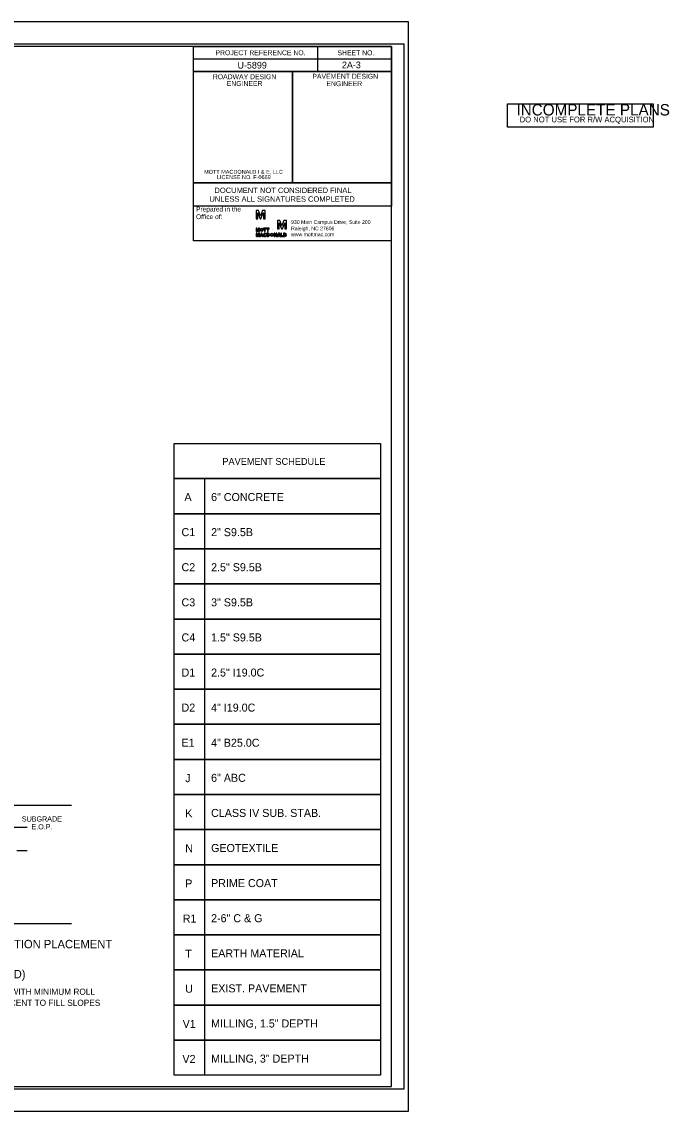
# Model space of a CAD drawing. Extents: x 1904401 to 1905163, y 193929 to 194736.
# Drawn here: x 1904969.4 to 1905100.1, y 194023.4 to 194243.4 of the extents above; entities that cross this region are included whole.
import ezdxf

# ---------------------------------------------------------------- set-up
doc = ezdxf.new("R2010")
doc.units = 0
for name, color, linetype in [('Old_Level_2', 7, 'Continuous'), ('Old_Level_42', 7, 'Continuous'), ('Old_Level_45', 7, 'Continuous'), ('Prop Dimension Text', 7, 'Continuous'), ('Prop Pavement Schedule Description CELL', 7, 'Continuous'), ('Sheet Cutting Line CELL', 7, 'Continuous'), ('Sheet Data Field CELL', 7, 'Continuous'), ('Sheet Plot Border Inside CELL', 7, 'Continuous'), ('Sheet Plot Border Outside CELL', 7, 'Continuous'), ('Sheet Sticker Exception Certification CELL', 7, 'Continuous'), ('Sheet Sticker Incomplete CELL', 7, 'Continuous'), ('Sheet Typical CELL', 7, 'Continuous')]:
    doc.layers.add(name, color=color, linetype=linetype)

msp = doc.modelspace()

# ---------------------------------------------------------------- linework, layer by layer
at = {"layer": 'Old_Level_2'}
for p, q in [((1905017.2, 194205.31), (1905016.7, 194205.31)), ((1905016.7, 194205.31), (1905016.7, 194203.62)), ((1905017.61, 194204.26), (1905017.2, 194205.31)), ((1905018.03, 194205.31), (1905017.62, 194204.26)), ((1905018.54, 194205.31), (1905018.03, 194205.31)), ((1905018.54, 194203.62), (1905018.54, 194205.31)), ((1905016.7, 194203.62), (1905017.06, 194203.62)), ((1905017.06, 194203.62), (1905017.06, 194204.84)), ((1905017.06, 194204.84), (1905017.06, 194204.84)), ((1905017.06, 194204.84), (1905017.54, 194203.62)), ((1905017.54, 194203.62), (1905017.7, 194203.62)), ((1905017.61, 194204.25), (1905017.61, 194204.26)), ((1905017.62, 194204.25), (1905017.61, 194204.25)), ((1905017.62, 194204.26), (1905017.62, 194204.25)), ((1905017.7, 194203.62), (1905018.17, 194204.84)), ((1905018.17, 194204.84), (1905018.18, 194204.84)), ((1905018.18, 194204.84), (1905018.18, 194203.62)), ((1905018.18, 194203.62), (1905018.54, 194203.62)), ((1905021.52, 194203.34), (1905021.02, 194203.34)), ((1905021.02, 194203.34), (1905021.02, 194201.64)), ((1905021.38, 194201.64), (1905021.38, 194202.86)), ((1905021.38, 194202.86), (1905021.38, 194202.86)), ((1905021.38, 194202.86), (1905021.86, 194201.64)), ((1905021.93, 194202.29), (1905021.52, 194203.34)), ((1905022.35, 194203.34), (1905021.94, 194202.29)), ((1905022.02, 194201.64), (1905022.49, 194202.86)), ((1905022.86, 194203.34), (1905022.35, 194203.34)), ((1905022.49, 194202.86), (1905022.5, 194202.86)), ((1905022.5, 194202.86), (1905022.5, 194201.64)), ((1905022.86, 194201.64), (1905022.86, 194203.34)), ((1905016.89, 194201.76), (1905016.7, 194201.76)), ((1905016.7, 194201.76), (1905016.7, 194201.11)), ((1905016.7, 194201.11), (1905016.83, 194201.11)), ((1905016.89, 194200.75), (1905016.7, 194200.75)), ((1905016.7, 194200.75), (1905016.7, 194200.1)), ((1905016.83, 194201.11), (1905016.83, 194201.57)), ((1905016.83, 194201.57), (1905016.84, 194201.57)), ((1905016.84, 194201.57), (1905017.02, 194201.11)), ((1905017.05, 194201.35), (1905016.89, 194201.76)), ((1905017.05, 194200.34), (1905016.89, 194200.75)), ((1905017.02, 194201.11), (1905017.08, 194201.11)), ((1905017.21, 194201.76), (1905017.05, 194201.35)), ((1905017.21, 194200.75), (1905017.05, 194200.34)), ((1905017.08, 194201.11), (1905017.27, 194201.57)), ((1905017.41, 194201.76), (1905017.21, 194201.76)), ((1905017.41, 194200.75), (1905017.21, 194200.75)), ((1905017.27, 194201.57), (1905017.27, 194201.57)), ((1905017.27, 194201.57), (1905017.27, 194201.11)), ((1905017.27, 194201.11), (1905017.41, 194201.11)), ((1905017.41, 194201.11), (1905017.41, 194201.76)), ((1905017.41, 194200.1), (1905017.41, 194200.75)), ((1905019.17, 194200.75), (1905018.88, 194200.75)), ((1905018.88, 194200.75), (1905018.88, 194200.41)), ((1905019.01, 194200.22), (1905019.01, 194200.63)), ((1905019.01, 194200.63), (1905019.17, 194200.63)), ((1905019.49, 194201.57), (1905019.5, 194201.57)), ((1905019.93, 194201.57), (1905019.93, 194201.57)), ((1905021.02, 194201.64), (1905021.38, 194201.64)), ((1905021.86, 194201.64), (1905022.02, 194201.64)), ((1905021.93, 194202.27), (1905021.93, 194202.29)), ((1905021.94, 194202.27), (1905021.93, 194202.27)), ((1905021.94, 194202.29), (1905021.94, 194202.27)), ((1905022.24, 194200.75), (1905022.24, 194200.75)), ((1905022.53, 194200.75), (1905022.24, 194200.75)), ((1905022.24, 194200.75), (1905022.24, 194200.41)), ((1905022.37, 194200.22), (1905022.37, 194200.63)), ((1905022.37, 194200.63), (1905022.53, 194200.63)), ((1905022.5, 194201.64), (1905022.86, 194201.64)), ((1905022.53, 194200.62), (1905022.53, 194200.62)), ((1905016.7, 194200.1), (1905016.83, 194200.1)), ((1905016.83, 194200.1), (1905016.83, 194200.57)), ((1905016.83, 194200.57), (1905016.84, 194200.57)), ((1905016.84, 194200.57), (1905017.02, 194200.1)), ((1905017.02, 194200.1), (1905017.08, 194200.1)), ((1905017.08, 194200.1), (1905017.27, 194200.57)), ((1905017.27, 194200.57), (1905017.27, 194200.57)), ((1905017.27, 194200.57), (1905017.27, 194200.1)), ((1905017.27, 194200.1), (1905017.41, 194200.1)), ((1905018.77, 194200.23), (1905018.66, 194200.29)), ((1905018.67, 194200.54), (1905018.79, 194200.59)), ((1905018.67, 194200.54), (1905018.79, 194200.59)), ((1905018.88, 194200.41), (1905018.88, 194200.1)), ((1905018.88, 194200.1), (1905019.17, 194200.1)), ((1905019.17, 194200.22), (1905019.01, 194200.22)), ((1905021.43, 194200.23), (1905021.32, 194200.29)), ((1905022.24, 194200.41), (1905022.24, 194200.1)), ((1905022.24, 194200.1), (1905022.53, 194200.1)), ((1905022.53, 194200.22), (1905022.37, 194200.22))]:
    msp.add_line(p, q, dxfattribs=at)
for points in [[(1905017.48, 194200.1), (1905017.64, 194200.1), (1905017.68, 194200.21), (1905017.96, 194200.21), (1905018, 194200.1), (1905018.15, 194200.1), (1905017.9, 194200.75), (1905017.73, 194200.75), (1905017.48, 194200.1)], [(1905017.72, 194200.33), (1905017.82, 194200.61), (1905017.93, 194200.33), (1905017.72, 194200.33)], [(1905018.22, 194201.64), (1905018.41, 194201.64), (1905018.41, 194201.11), (1905018.55, 194201.11), (1905018.55, 194201.64), (1905018.74, 194201.64), (1905018.74, 194201.76), (1905018.22, 194201.76), (1905018.22, 194201.64)], [(1905018.82, 194201.64), (1905019.01, 194201.64), (1905019.01, 194201.11), (1905019.15, 194201.11), (1905019.15, 194201.64), (1905019.33, 194201.64), (1905019.33, 194201.76), (1905018.82, 194201.76), (1905018.82, 194201.64)], [(1905020.47, 194200.52), (1905020.47, 194200.52), (1905020.78, 194200.1), (1905020.91, 194200.1), (1905020.91, 194200.75), (1905020.78, 194200.75), (1905020.78, 194200.34), (1905020.47, 194200.75), (1905020.34, 194200.75), (1905020.34, 194200.1), (1905020.47, 194200.1), (1905020.47, 194200.52)], [(1905020.99, 194200.1), (1905021.15, 194200.1), (1905021.19, 194200.21), (1905021.47, 194200.21), (1905021.51, 194200.1), (1905021.66, 194200.1), (1905021.42, 194200.75), (1905021.24, 194200.75), (1905020.99, 194200.1)], [(1905021.23, 194200.33), (1905021.33, 194200.61), (1905021.44, 194200.33), (1905021.23, 194200.33)], [(1905022.16, 194200.1), (1905022.16, 194200.21), (1905021.88, 194200.21), (1905021.88, 194200.75), (1905021.74, 194200.75), (1905021.74, 194200.1), (1905022.16, 194200.1)]]:
    msp.add_lwpolyline(points, dxfattribs=at)
msp.add_arc((1905022.53, 194200.42), 0.325, 270, 90, dxfattribs=at)
for centre, major_axis, ratio in [((1905017.85, 194201.43), (0, 0.325), 0.993118), ((1905017.85, 194201.43), (0, 0.211), 0.916103), ((1905019.9, 194200.42), (0, 0.325), 0.993118), ((1905019.9, 194200.42), (0, 0.211), 0.916103)]:
    msp.add_ellipse(centre, major_axis=major_axis, ratio=ratio, dxfattribs=at)
for centre, major_axis, ratio, start_param, end_param in [((1905018.51, 194200.42), (0, 0.325), 0.993118, 5.246647, 10.366427), ((1905018.51, 194200.42), (0, 0.211), 0.916103, 5.276876, 10.296021), ((1905019.17, 194200.42), (0, -0.324), 0.930276, 0, 3.141593), ((1905019.17, 194200.43), (0, -0.203), 0.900832, 0, 3.141593), ((1905022.53, 194200.43), (0, -0.203), 0.900832, 0, 3.141593)]:
    msp.add_ellipse(centre, major_axis=major_axis, ratio=ratio, start_param=start_param, end_param=end_param, dxfattribs=at)
at = {"layer": 'Old_Level_42'}
msp.add_lwpolyline([(1905044.05, 194199.18), (1905004.08, 194199.18), (1905004.08, 194206.23)], dxfattribs=at)
at = {"layer": 'Prop Dimension Text'}
for p, q in [((1904970.47, 194080.72), (1904967.5, 194080.72)), ((1904970.47, 194076.02), (1904968.39, 194076.02))]:
    msp.add_line(p, q, dxfattribs=at)
for points in [[(1904979.44, 194085.19), (1904951.83, 194085.19), (1904951.21, 194086.17), (1904950.82, 194084.34), (1904950.18, 194085.19), (1904924.97, 194085.19)], [(1904979.44, 194061.29), (1904951.83, 194061.29), (1904951.21, 194062.26), (1904950.82, 194060.44), (1904950.18, 194061.28), (1904924.97, 194061.28)]]:
    msp.add_lwpolyline(points, dxfattribs=at)
at = {"layer": 'Prop Pavement Schedule Description CELL'}
msp.add_lwpolyline([(1905000.16, 194158.28), (1905041.87, 194158.28), (1905041.87, 194151.19), (1905000.16, 194151.19)], close=True, dxfattribs=at)
for points in [[(1905006.34, 194144.1), (1905000.16, 194144.1), (1905000.16, 194151.19), (1905041.87, 194151.19), (1905041.87, 194144.1), (1905006.34, 194144.1), (1905006.34, 194151.19)], [(1905006.34, 194137.02), (1905000.16, 194137.02), (1905000.16, 194144.1), (1905041.87, 194144.1), (1905041.87, 194137.02), (1905006.34, 194137.02), (1905006.34, 194144.1)], [(1905006.34, 194129.93), (1905000.16, 194129.93), (1905000.16, 194137.02), (1905041.87, 194137.02), (1905041.87, 194129.93), (1905006.34, 194129.93), (1905006.34, 194137.02)], [(1905006.34, 194122.84), (1905000.16, 194122.84), (1905000.16, 194129.93), (1905041.87, 194129.93), (1905041.87, 194122.84), (1905006.34, 194122.84), (1905006.34, 194129.93)], [(1905006.34, 194115.76), (1905000.16, 194115.76), (1905000.16, 194122.84), (1905041.87, 194122.84), (1905041.87, 194115.76), (1905006.34, 194115.76), (1905006.34, 194122.84)], [(1905006.34, 194108.67), (1905000.16, 194108.67), (1905000.16, 194115.76), (1905041.87, 194115.76), (1905041.87, 194108.67), (1905006.34, 194108.67), (1905006.34, 194115.76)], [(1905006.34, 194101.58), (1905000.16, 194101.58), (1905000.16, 194108.67), (1905041.87, 194108.67), (1905041.87, 194101.58), (1905006.34, 194101.58), (1905006.34, 194108.67)], [(1905006.34, 194094.49), (1905000.16, 194094.49), (1905000.16, 194101.58), (1905041.87, 194101.58), (1905041.87, 194094.49), (1905006.34, 194094.49), (1905006.34, 194101.58)], [(1905006.34, 194087.41), (1905000.16, 194087.41), (1905000.16, 194094.49), (1905041.87, 194094.49), (1905041.87, 194087.41), (1905006.34, 194087.41), (1905006.34, 194094.49)], [(1905006.34, 194080.32), (1905000.16, 194080.32), (1905000.16, 194087.41), (1905041.87, 194087.41), (1905041.87, 194080.32), (1905006.34, 194080.32), (1905006.34, 194087.41)], [(1905006.34, 194073.23), (1905000.16, 194073.23), (1905000.16, 194080.32), (1905041.87, 194080.32), (1905041.87, 194073.23), (1905006.34, 194073.23), (1905006.34, 194080.32)], [(1905006.34, 194066.14), (1905000.16, 194066.14), (1905000.16, 194073.23), (1905041.87, 194073.23), (1905041.87, 194066.14), (1905006.34, 194066.14), (1905006.34, 194073.23)], [(1905006.34, 194059.06), (1905000.16, 194059.06), (1905000.16, 194066.14), (1905041.87, 194066.14), (1905041.87, 194059.06), (1905006.34, 194059.06), (1905006.34, 194066.14)], [(1905006.34, 194051.97), (1905000.16, 194051.97), (1905000.16, 194059.06), (1905041.87, 194059.06), (1905041.87, 194051.97), (1905006.34, 194051.97), (1905006.34, 194059.06)], [(1905006.34, 194044.88), (1905000.16, 194044.88), (1905000.16, 194051.97), (1905041.87, 194051.97), (1905041.87, 194044.88), (1905006.34, 194044.88), (1905006.34, 194051.97)], [(1905006.34, 194037.79), (1905000.16, 194037.79), (1905000.16, 194044.88), (1905041.87, 194044.88), (1905041.87, 194037.79), (1905006.34, 194037.79), (1905006.34, 194044.88)], [(1905006.34, 194030.71), (1905000.16, 194030.71), (1905000.16, 194037.79), (1905041.87, 194037.79), (1905041.87, 194030.71), (1905006.34, 194030.71), (1905006.34, 194037.79)]]:
    msp.add_lwpolyline(points, dxfattribs=at)
at = {"layer": 'Sheet Cutting Line CELL'}
for p, q in [((1905047.49, 194243.44), (1904710.69, 194243.44)), ((1904710.69, 194023.44), (1905047.49, 194023.44))]:
    msp.add_line(p, q, dxfattribs=at)
at = {"layer": 'Sheet Plot Border Inside CELL'}
msp.add_lwpolyline([(1905046.59, 194238.95), (1904713.29, 194238.95), (1904713.29, 194027.93), (1905046.59, 194027.93)], close=True, dxfattribs=at)
at = {"layer": 'Sheet Plot Border Outside CELL'}
msp.add_lwpolyline([(1905047.49, 194243.44), (1904710.69, 194243.44), (1904710.69, 194023.44), (1905047.49, 194023.44)], close=True, dxfattribs=at)
at = {"layer": 'Sheet Sticker Exception Certification CELL'}
for p, q in [((1905004.08, 194206.23), (1905004.08, 194210.93)), ((1905004.08, 194210.93), (1905044.09, 194210.93)), ((1905044.09, 194210.93), (1905044.09, 194206.23)), ((1905044.09, 194206.23), (1905004.08, 194206.23))]:
    msp.add_line(p, q, dxfattribs=at)
at = {"layer": 'Sheet Sticker Incomplete CELL'}
msp.add_lwpolyline([(1905067.5, 194222.18), (1905067.5, 194226.88), (1905096.9, 194226.88), (1905096.9, 194222.18)], close=True, dxfattribs=at)
at = {"layer": 'Sheet Typical CELL'}
for p, q in [((1905029.09, 194238.43), (1905029.09, 194233.43)), ((1905004.08, 194235.93), (1905044.09, 194235.93)), ((1905024.09, 194233.43), (1905024.09, 194210.94))]:
    msp.add_line(p, q, dxfattribs=at)
for points in [[(1905044.09, 194238.44), (1904744.09, 194238.44), (1904744.09, 194028.44), (1905044.09, 194028.44)], [(1905004.08, 194238.44), (1905044.09, 194238.44), (1905044.09, 194233.43), (1905004.08, 194233.43)], [(1905004.08, 194233.43), (1905024.09, 194233.43), (1905024.09, 194210.93), (1905004.08, 194210.93)], [(1905024.09, 194233.43), (1905044.09, 194233.43), (1905044.09, 194210.93), (1905024.09, 194210.93)]]:
    msp.add_lwpolyline(points, close=True, dxfattribs=at)

# ---------------------------------------------------------------- texts
at = {"layer": 'Old_Level_2'}
for s, height, p in [('Prepared in the ', 0.9628, (1905004.59, 194205.13)), ('Office of:', 0.963, (1905004.59, 194203.59)), ('930 Main Campus Drive, Suite 200', 0.7492, (1905023.78, 194202.63)), ('www.mottmac.com', 0.7492, (1905023.78, 194200.13)), ('Raleigh, NC 27606', 0.7492, (1905023.78, 194201.34))]:
    msp.add_text(s, height=height, rotation=360, dxfattribs=at).set_placement(p)
at = {"layer": 'Old_Level_45'}
for s, p in [('MOTT MACDONALD I & E, LLC', (1905006.22, 194212.74)), (' LICENSE NO. F-0669', (1905008.5, 194211.67))]:
    msp.add_text(s, height=0.8036, dxfattribs=at).set_placement(p)
at = {"layer": 'Prop Dimension Text'}
for s, height, p in [('SUBGRADE', 1.046, (1904969.41, 194081.94)), ('E.O.P.', 1.046, (1904971.36, 194080.37)), ('GEOTEXTILE FOR SUBGRADE STABILIZATION PLACEMENT', 1.6899, (1904923, 194056.35)), ('(100% COVERAGE REQUIRED)', 1.6899, (1904936.88, 194050.28)), ('*INSTALL GEOTEXTILE FOR SUBGRADE STABILIZATION WITH MINIMUM ROLL', 1.2478, (1904921.7, 194046.95)), ('WIDTH UNDER ROADWAY EDGES AND SHOULDERS ADJACENT TO FILL SLOPES', 1.2478, (1904920.17, 194044.72))]:
    msp.add_text(s, height=height, dxfattribs=at).set_placement(p)
at = {"layer": 'Prop Pavement Schedule Description CELL'}
for s, height, p in [('PAVEMENT SCHEDULE', 1.386, (1905009.91, 194153.96)), ('A', 1.62, (1905002.25, 194146.66)), ('6" CONCRETE', 1.6162, (1905007.63, 194146.66)), ('C1', 1.616, (1905001.66, 194139.57)), ('2" S9.5B', 1.616, (1905007.63, 194139.57)), ('C2', 1.616, (1905001.66, 194132.49)), ('2.5" S9.5B', 1.616, (1905007.63, 194132.49)), ('C3', 1.616, (1905001.66, 194125.4)), ('3" S9.5B', 1.616, (1905007.63, 194125.4)), ('C4', 1.616, (1905001.66, 194118.31)), ('1.5" S9.5B', 1.616, (1905007.63, 194118.31)), ('D1', 1.616, (1905001.66, 194111.22)), ('2.5" I19.0C', 1.6162, (1905007.63, 194111.22)), ('D2', 1.616, (1905001.66, 194104.14)), ('4" I19.0C', 1.616, (1905007.63, 194104.14)), ('E1', 1.616, (1905001.66, 194097.05)), ('4" B25.0C', 1.616, (1905007.63, 194097.05)), ('J', 1.62, (1905002.41, 194089.89)), ('6" ABC', 1.616, (1905007.63, 194089.96)), ('K', 1.62, (1905002.41, 194082.8)), ('CLASS IV SUB. STAB.', 1.6162, (1905007.63, 194082.87)), ('GEOTEXTILE', 1.616, (1905007.63, 194075.79)), ('N', 1.62, (1905002.41, 194075.72)), ('P', 1.62, (1905002.41, 194068.63)), ('PRIME COAT', 1.616, (1905007.63, 194068.7)), ('R1', 1.616, (1905001.9, 194061.55)), ('2-6" C & G', 1.616, (1905007.63, 194061.61)), ('T ', 1.616, (1905002.41, 194054.45)), ('EARTH MATERIAL', 1.6162, (1905007.63, 194054.52)), ('U ', 1.616, (1905002.41, 194047.37)), ('EXIST. PAVEMENT', 1.6162, (1905007.63, 194047.44)), ('V1', 1.616, (1905001.89, 194040.28)), ('MILLING, 1.5" DEPTH', 1.6162, (1905007.63, 194040.35)), ('V2', 1.616, (1905001.84, 194033.19)), ('MILLING, 3" DEPTH', 1.6162, (1905007.63, 194033.26))]:
    msp.add_text(s, height=height, dxfattribs=at).set_placement(p)
at = {"layer": 'Sheet Data Field CELL'}
for s, p in [('U-5899', (1905012.96, 194234)), ('2A-3', (1905034.05, 194234.06))]:
    msp.add_text(s, height=1.35, dxfattribs=at).set_placement(p)
at = {"layer": 'Sheet Sticker Exception Certification CELL'}
for s, p in [('DOCUMENT NOT CONSIDERED FINAL', (1905008.3, 194208.86)), ('UNLESS ALL SIGNATURES COMPLETED', (1905007.28, 194207.1))]:
    msp.add_text(s, height=1.1, dxfattribs=at).set_placement(p)
at = {"layer": 'Sheet Sticker Incomplete CELL'}
for s, height, p in [('INCOMPLETE PLANS', 2.304, (1905069.29, 194224.52)), ('DO NOT USE FOR R/W ACQUISITION', 1.152, (1905069.94, 194223.13))]:
    msp.add_text(s, height=height, dxfattribs=at).set_placement(p)
at = {"layer": 'Sheet Typical CELL'}
for s, p in [('PROJECT REFERENCE NO.', (1905008.52, 194236.7)), ('SHEET NO.', (1905033.15, 194236.68)), ('ROADWAY DESIGN', (1905007.98, 194231.85)), ('ENGINEER', (1905010.79, 194230.48)), ('PAVEMENT DESIGN', (1905028.08, 194231.94)), ('ENGINEER', (1905030.92, 194230.45))]:
    msp.add_text(s, height=1, dxfattribs=at).set_placement(p)

doc.saveas('drawing.dxf')
